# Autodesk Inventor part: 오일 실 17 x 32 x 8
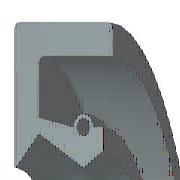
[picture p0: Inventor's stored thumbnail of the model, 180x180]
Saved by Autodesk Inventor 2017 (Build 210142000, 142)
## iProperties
Created: 2012-02
Part Number: 오일 실 17 x 32 x 8
Material: 고무
Description: 샤프트 실 링
Document SubType Name: Modeling
Standard: JIS B 2402
Designer: mdu-01
Standards Organization: JIS
Language: ko-KR
Size Designation: D 17 x 32 x 8
Categories: <MemberInstance><Categories><Category DisplayName="샤프트 부품" InternalName="7f7aeb1f-a693-4053-b835-cee3144e0d98" Mnemonic="SHFT"><Category DisplayName="실링" Intern
Density: 0.93 g/cm^3
Mass: 2.28027 g
Surface Area: 32.1224 cm^2
Volume: 2.45191 cm^3
Appearance: 고무 - 검은색 - 버전 1.1
IsCustomPart: 1
Author: mdu-01
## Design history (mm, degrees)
revolve "본체" stored, may be unused: angle "d17" = 90 deg
revolve "스프링1" stored, may be unused: angle "d18" = 90 deg
body "Solid1"
sketch "스케치1"
  geometry: L1 (0, 16)-(8, 16); L2 (8, 14.25)-(1.75, 14.25); L3 (1.75, 10.25)-(4.9, 8.5); L4 (4.9, 8.5)-(0, 8.5); L5 (0, 0)-(9.586, 0) reference; L6 (4.9, 8.5)-(6.3, 9.375); L7 (0, 18)-(0, -3) reference; L8 (-1.941, 0)-(11.507, 0) reference; L9 (4.2, 10.6)-(1.75, 11.21); L10 (1.75, 11.21)-(1.75, 14.25); L11 (0, 16)-(0, 8.588); L12 (4.9, 8.5)-(0, 8.5); L13 (1.75, 10.25)-(0.152, 8.528); L14 (8, 16)-(8, 14.25); L15 (5.6, 10.6)-(6.3, 10.6); L16 (6.3, 10.6)-(6.3, 9.375); C1 r 0.455 at (4.9, 10.6); A1 r 0.7 centre (4.9, 10.6) between (5.6, 10.6) and (4.2, 10.6); A2 r 0.088 centre (0.088, 8.588) between (0, 8.588) and (0.152, 8.528); 1 further point
  constraints: 28 end point, 5 horizontal alignment, 5 point on line, 4 point on circle, 4 vertical alignment, 3 centre point, 3 tangent, 2 collinear, 2 horizontal, 2 perpendicular, 1 coincident, 1 parallel
  dimensions: "d0" = 32 diameter of L1 L5 (= SD2); "d1" = 1.75 distance of L1.end L2.start (= SD); "d2" = 0.91 diameter of C1 (= SPDI); "d3" = 1.4 diameter of A1 (= SPDA); "d4" = 17 diameter of L3.end L5 (= NND); "d5" = 20.5 diameter of L3.start L5 (= TKDM); "d7" = 22.42 diameter of L9.end L5 (= TKDM + 0.24 x SWDT); "d8" = 1.75 distance between parallel lines of L11 L10 (= SD); "d9" = 4.9 distance from line of L11 C1.centre (= SPDST); "d10" = 21.2 diameter of C1.centre L5 (= HLDM); "d11" = 0.0875 radius of A2 (= 0.25 x LAB); "d12" = 6.3 distance between parallel lines of L11 L16 (= SDI); "d13" = 18.75 diameter of L6.end L5 (= ABDM); "d14" = 8 distance from line of L11 L1.end (= SWDT)
fillet "모깎기1" dims "d6" = 0.3 (= RR)
other parameters: "SD2" = 32 [user parameter; used in 1 equation term], "SWDT" = 8 [user parameter; used in 2 equation terms], "RR" = 0.3 [user parameter; used in 1 equation term], "SD" = 1.75 [user parameter; used in 2 equation terms], "NND" = 17 [user parameter; used in 1 equation term], "SPDA" = 1.4 [user parameter; used in 1 equation term], "SPDI" = 0.91 [user parameter; used in 1 equation term], "TKDM" = 20.5 [user parameter; used in 2 equation terms], "HLDM" = 21.2 [user parameter; used in 1 equation term], "ABDM" = 18.75 [user parameter; used in 1 equation term], "SDI" = 6.3 [user parameter; used in 1 equation term], "SPDST" = 4.9 [user parameter; used in 1 equation term], "LAB" = 0.35 [user parameter; used in 1 equation term], "d15" = 0, "d16" = 0, "d19" = 0
